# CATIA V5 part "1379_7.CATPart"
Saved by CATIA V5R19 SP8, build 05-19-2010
Part number: 7
Bounding box of the stored display mesh (mm): x -3.5 to -1.5, y 42.5 to 51.5, z 7.5 to 44.5
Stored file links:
  C:\Users\ThinkMotion\Desktop\EU_thinkMotion\iao\IAO_MMS_Groupe3\bblot\bblot\1379_7.CATPart
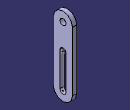
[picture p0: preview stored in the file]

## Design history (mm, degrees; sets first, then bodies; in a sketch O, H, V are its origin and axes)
Parameters
  Rainure = 19 mm
Body1 (main body)
  Plane1: stored without definition
  Line1: stored without definition
  Point1: stored without definition
  Point2: stored without definition
  Sketch1 on Plane1, origin (-1.5, 0, 0), H (0, 1, 0), V (0, 0, 1)
    construction line L1 (47, 40) -> (47, 12)
    point P1 (47, 40)
    line L2 (51.5, 40) -> (51.5, 12)
    line L3 (42.5, 12) -> (42.5, 40)
    arc A1 centre (47, 12) radius 4.5 from (51.5, 12) to (42.5, 12) cw
    arc A2 centre (47, 40) radius 4.5 from (42.5, 40) to (51.5, 40) cw
    construction line L4 (47, 28) -> (47, 12)
    point P7 (47, 28)
    line L5 (48.5, 28) -> (48.5, 12)
    line L6 (45.5, 12) -> (45.5, 28)
    arc A3 centre (47, 12) radius 1.5 from (48.5, 12) to (45.5, 12) cw
    arc A4 centre (47, 28) radius 1.5 from (45.5, 28) to (48.5, 28) cw
    reference projected line E1 through (47, 0) direction (0, 1) from Line1
    reference projected point E2 (47, 28) from Point1
    reference projected point E3 (47, 40) from Point2
    circle A5 centre (47, 40) radius 1.5
    point P12 (47, 41.5)
    distance L1 L2 = 4.5
    distance L4 L5 = 1.5
    distance A4 A3 = 19 {= Rainure}
    vertical: L1 V, L4 V
    tangency: A1 L2, A2 L2, A1 L3, A2 L3, A3 L5, A4 L5, A3 L6, A4 L6, L5 A5
    coincidence: P7 L1, L1 E1, P7 E2, P1 E3, A5 P12, P12 L1
  Pad1: profile Sketch1, direction (-1, 0, 0), length 2
  Point3: type Center, Curve edge [start face of Pad1 | face of Pad1 from Sketch1.A3]
  Point4: type Center, Curve edge [start face of Pad1 | face of Pad1 from Sketch1.A4]
  Line2: type PtPt, FirstPoint Point4, SecondPoint Point3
